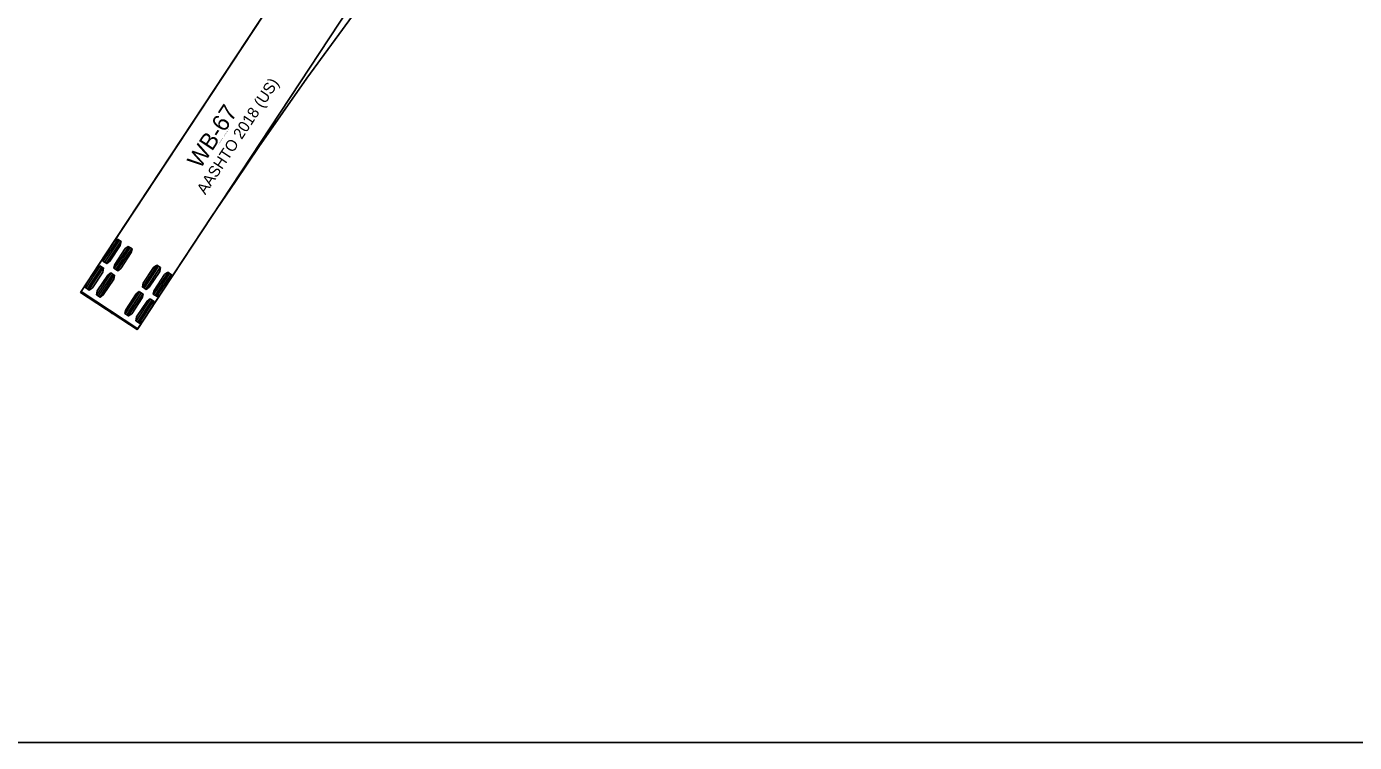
# Model space of a CAD drawing. Extents: x 973688 to 979179, y 703586 to 707602.
# Drawn here: x 973925.7 to 974092.8, y 707124.2 to 707214.3 of the extents above; entities that cross this region are included whole.
import ezdxf

# ---------------------------------------------------------------- set-up
doc = ezdxf.new("R2010")
doc.units = 0
doc.layers.add('0-NPLT', color=7, linetype='Continuous')
doc.layers.add('NO PLOT', color=7, linetype='Continuous')

msp = doc.modelspace()

# ---------------------------------------------------------------- linework, layer by layer
at = {"layer": '0-NPLT'}
for p, q in [((973937.16, 707187.5), (973935.35, 707184.74)), ((973937.16, 707187.5), (973935.35, 707184.74)), ((973937.36, 707187.37), (973935.54, 707184.62)), ((973937.36, 707187.37), (973935.54, 707184.62)), ((973937.55, 707187.25), (973935.73, 707184.49)), ((973937.55, 707187.25), (973935.73, 707184.49)), ((973938.54, 707186.59), (973936.73, 707183.84)), ((973938.54, 707186.59), (973936.73, 707183.84)), ((973938.73, 707186.47), (973936.92, 707183.71)), ((973938.73, 707186.47), (973936.92, 707183.71)), ((973938.92, 707186.34), (973937.11, 707183.58)), ((973938.92, 707186.34), (973937.11, 707183.58)), ((973934.96, 707184.16), (973933.15, 707181.4)), ((973934.96, 707184.16), (973933.15, 707181.4)), ((973935.16, 707184.03), (973933.34, 707181.28)), ((973935.16, 707184.03), (973933.34, 707181.28)), ((973935.35, 707183.91), (973933.53, 707181.15)), ((973935.35, 707183.91), (973933.53, 707181.15)), ((973936.34, 707183.25), (973934.53, 707180.5)), ((973936.34, 707183.25), (973934.53, 707180.5)), ((973936.53, 707183.13), (973934.72, 707180.37)), ((973936.53, 707183.13), (973934.72, 707180.37)), ((973936.72, 707183), (973934.91, 707180.24)), ((973936.72, 707183), (973934.91, 707180.24)), ((973942.12, 707184.24), (973940.3, 707181.48)), ((973942.12, 707184.24), (973940.3, 707181.48)), ((973942.31, 707184.11), (973940.5, 707181.35)), ((973942.31, 707184.11), (973940.5, 707181.35)), ((973942.5, 707183.98), (973940.69, 707181.23)), ((973942.5, 707183.98), (973940.69, 707181.23)), ((973943.5, 707183.33), (973941.68, 707180.57)), ((973943.5, 707183.33), (973941.68, 707180.57)), ((973943.69, 707183.2), (973941.87, 707180.45)), ((973943.69, 707183.2), (973941.87, 707180.45)), ((973943.88, 707183.08), (973942.06, 707180.32)), ((973943.88, 707183.08), (973942.06, 707180.32)), ((973939.67, 707176.26), (973932.57, 707180.94)), ((973939.67, 707176.26), (973932.57, 707180.94)), ((973939.92, 707180.89), (973938.1, 707178.14)), ((973939.92, 707180.89), (973938.1, 707178.14)), ((973940.11, 707180.77), (973938.3, 707178.01)), ((973940.11, 707180.77), (973938.3, 707178.01)), ((973940.3, 707180.64), (973938.49, 707177.89)), ((973940.3, 707180.64), (973938.49, 707177.89)), ((973941.3, 707179.99), (973939.48, 707177.23)), ((973941.3, 707179.99), (973939.48, 707177.23)), ((973941.49, 707179.86), (973939.67, 707177.11)), ((973941.49, 707179.86), (973939.67, 707177.11)), ((973941.68, 707179.74), (973939.86, 707176.98)), ((973941.68, 707179.74), (973939.86, 707176.98)), ((973935.86, 707178.69), (973935.63, 707178.83)), ((973935.86, 707178.69), (973935.63, 707178.83)), ((973936.08, 707178.54), (973936.12, 707178.6)), ((973936.08, 707178.54), (973936.12, 707178.6)), ((973936.52, 707178.25), (973936.3, 707178.39)), ((973936.52, 707178.25), (973936.3, 707178.39))]:
    msp.add_line(p, q, dxfattribs=at)
for points in [[(973932.49, 707180.82), (973962.34, 707226.13)], [(973932.49, 707180.82), (973962.34, 707226.13)], [(973939.61, 707176.21), (973939.63, 707176.2), (973939.67, 707176.26), (973942.78, 707180.99), (973968.74, 707220.4), (973965.19, 707222.74), (973961.64, 707225.08), (973935.68, 707185.67), (973932.57, 707180.94), (973932.53, 707180.88), (973932.55, 707180.87)], [(973939.61, 707176.21), (973939.63, 707176.2), (973939.67, 707176.26), (973942.78, 707180.99), (973968.74, 707220.4), (973965.19, 707222.74), (973961.64, 707225.08), (973935.68, 707185.67), (973932.57, 707180.94), (973932.53, 707180.88), (973932.55, 707180.87)], [(973967.16, 707216.24), (973964.04, 707212.03), (973960.97, 707207.78), (973957.93, 707203.48), (973954.93, 707199.16), (973951.96, 707194.8), (973949.02, 707190.41), (973943.16, 707181.56), (973939.59, 707176.14), (973932.49, 707180.82), (973932.49, 707180.82)], [(973967.16, 707216.24), (973964.04, 707212.03), (973960.97, 707207.78), (973957.93, 707203.48), (973954.93, 707199.16), (973951.96, 707194.8), (973949.02, 707190.41), (973943.16, 707181.56), (973939.59, 707176.14), (973932.49, 707180.82), (973932.49, 707180.82)], [(973932.57, 707180.85), (973932.57, 707180.85), (973935.6, 707178.85), (973935.63, 707178.83), (973935.6, 707178.77), (973935.6, 707178.77), (973935.82, 707178.63)], [(973932.57, 707180.85), (973932.57, 707180.85), (973935.6, 707178.85), (973935.63, 707178.83), (973935.6, 707178.77), (973935.6, 707178.77), (973935.82, 707178.63)], [(973935.86, 707178.68), (973936.3, 707178.4)], [(973935.86, 707178.68), (973936.3, 707178.4)], [(973936.26, 707178.34), (973936.48, 707178.19), (973936.48, 707178.19), (973936.52, 707178.25), (973936.55, 707178.23), (973939.59, 707176.23), (973939.59, 707176.23)], [(973936.26, 707178.34), (973936.48, 707178.19), (973936.48, 707178.19), (973936.52, 707178.25), (973936.55, 707178.23), (973939.59, 707176.23), (973939.59, 707176.23)]]:
    msp.add_lwpolyline(points, dxfattribs=at)
for points in [[(973937.12, 707187.53), (973937.59, 707187.22), (973937.48, 707186.74), (973936.18, 707184.75), (973935.78, 707184.46), (973935.3, 707184.77), (973935.41, 707185.26), (973936.72, 707187.24)], [(973937.12, 707187.53), (973937.59, 707187.22), (973937.48, 707186.74), (973936.18, 707184.75), (973935.78, 707184.46), (973935.3, 707184.77), (973935.41, 707185.26), (973936.72, 707187.24)], [(973938.49, 707186.62), (973938.97, 707186.31), (973938.86, 707185.83), (973937.56, 707183.84), (973937.16, 707183.55), (973936.68, 707183.87), (973936.79, 707184.35), (973938.1, 707186.33)], [(973938.49, 707186.62), (973938.97, 707186.31), (973938.86, 707185.83), (973937.56, 707183.84), (973937.16, 707183.55), (973936.68, 707183.87), (973936.79, 707184.35), (973938.1, 707186.33)], [(973934.92, 707184.19), (973935.39, 707183.88), (973935.28, 707183.39), (973933.98, 707181.41), (973933.58, 707181.12), (973933.1, 707181.43), (973933.21, 707181.91), (973934.52, 707183.9)], [(973934.92, 707184.19), (973935.39, 707183.88), (973935.28, 707183.39), (973933.98, 707181.41), (973933.58, 707181.12), (973933.1, 707181.43), (973933.21, 707181.91), (973934.52, 707183.9)], [(973936.29, 707183.28), (973936.77, 707182.97), (973936.66, 707182.49), (973935.35, 707180.5), (973934.96, 707180.21), (973934.48, 707180.53), (973934.59, 707181.01), (973935.9, 707182.99)], [(973936.29, 707183.28), (973936.77, 707182.97), (973936.66, 707182.49), (973935.35, 707180.5), (973934.96, 707180.21), (973934.48, 707180.53), (973934.59, 707181.01), (973935.9, 707182.99)], [(973942.07, 707184.27), (973942.55, 707183.95), (973942.44, 707183.47), (973941.13, 707181.49), (973940.73, 707181.2), (973940.26, 707181.51), (973940.37, 707181.99), (973941.67, 707183.98)], [(973942.07, 707184.27), (973942.55, 707183.95), (973942.44, 707183.47), (973941.13, 707181.49), (973940.73, 707181.2), (973940.26, 707181.51), (973940.37, 707181.99), (973941.67, 707183.98)], [(973943.45, 707183.36), (973943.93, 707183.04), (973943.82, 707182.56), (973942.51, 707180.58), (973942.11, 707180.29), (973941.63, 707180.6), (973941.74, 707181.08), (973943.05, 707183.07)], [(973943.45, 707183.36), (973943.93, 707183.04), (973943.82, 707182.56), (973942.51, 707180.58), (973942.11, 707180.29), (973941.63, 707180.6), (973941.74, 707181.08), (973943.05, 707183.07)], [(973939.87, 707180.93), (973940.35, 707180.61), (973940.24, 707180.13), (973938.93, 707178.15), (973938.53, 707177.86), (973938.06, 707178.17), (973938.17, 707178.65), (973939.47, 707180.64)], [(973939.87, 707180.93), (973940.35, 707180.61), (973940.24, 707180.13), (973938.93, 707178.15), (973938.53, 707177.86), (973938.06, 707178.17), (973938.17, 707178.65), (973939.47, 707180.64)], [(973941.25, 707180.02), (973941.73, 707179.7), (973941.62, 707179.22), (973940.31, 707177.24), (973939.91, 707176.95), (973939.43, 707177.26), (973939.54, 707177.74), (973940.85, 707179.73)], [(973941.25, 707180.02), (973941.73, 707179.7), (973941.62, 707179.22), (973940.31, 707177.24), (973939.91, 707176.95), (973939.43, 707177.26), (973939.54, 707177.74), (973940.85, 707179.73)]]:
    msp.add_lwpolyline(points, close=True, dxfattribs=at)
for centre in [(973932.54, 707180.83), (973932.54, 707180.83), (973939.58, 707176.19), (973939.58, 707176.19)]:
    msp.add_circle(centre, 0.0266, dxfattribs=at)
for centre, radius, start, end in [((973932.54, 707180.83), 0.0363, 75.7046, 36.8659), ((973932.54, 707180.83), 0.0363, 75.7046, 36.8659), ((973935.84, 707178.66), 0.0353, 59.9633, 238.3129), ((973935.84, 707178.66), 0.0353, 59.9633, 238.3129), ((973935.84, 707178.66), 0.0352, 236.6524, 55.6528), ((973935.84, 707178.66), 0.0352, 236.6524, 55.6528), ((973936.28, 707178.37), 0.0352, 57.6014, 236.6018), ((973936.28, 707178.37), 0.0352, 57.6014, 236.6018), ((973936.28, 707178.37), 0.0354, 240.9186, 53.1041), ((973936.28, 707178.37), 0.0354, 240.9186, 53.1041), ((973938.5, 707174.53), 2.02, 56.6271, 57.3109), ((973938.5, 707174.53), 2.02, 56.6271, 57.3109)]:
    msp.add_arc(centre, radius, start, end, dxfattribs=at)
at = {"layer": 'NO PLOT'}
msp.add_lwpolyline([(973688.49, 707564.2), (974368.49, 707564.2), (974368.49, 707124.2), (973688.49, 707124.2)], close=True, dxfattribs=at)

# ---------------------------------------------------------------- texts
at = {"layer": '0-NPLT'}
for s, height, p in [('AASHTO 2018 (US)', 1.4167, (973948.18, 707193.04)), ('AASHTO 2018 (US)', 1.4167, (973948.18, 707193.04)), ('WB-67', 2.125, (973947.55, 707196.27)), ('WB-67', 2.125, (973947.55, 707196.27)), ('(c) 2021 Transoft Solutions, Inc. All rights reserved.', 0.085, (973949.7, 707199.14)), ('(c) 2021 Transoft Solutions, Inc. All rights reserved.', 0.085, (973949.7, 707199.14))]:
    msp.add_text(s, height=height, rotation=56.6271, dxfattribs=at).set_placement(p)

doc.saveas('drawing.dxf')
